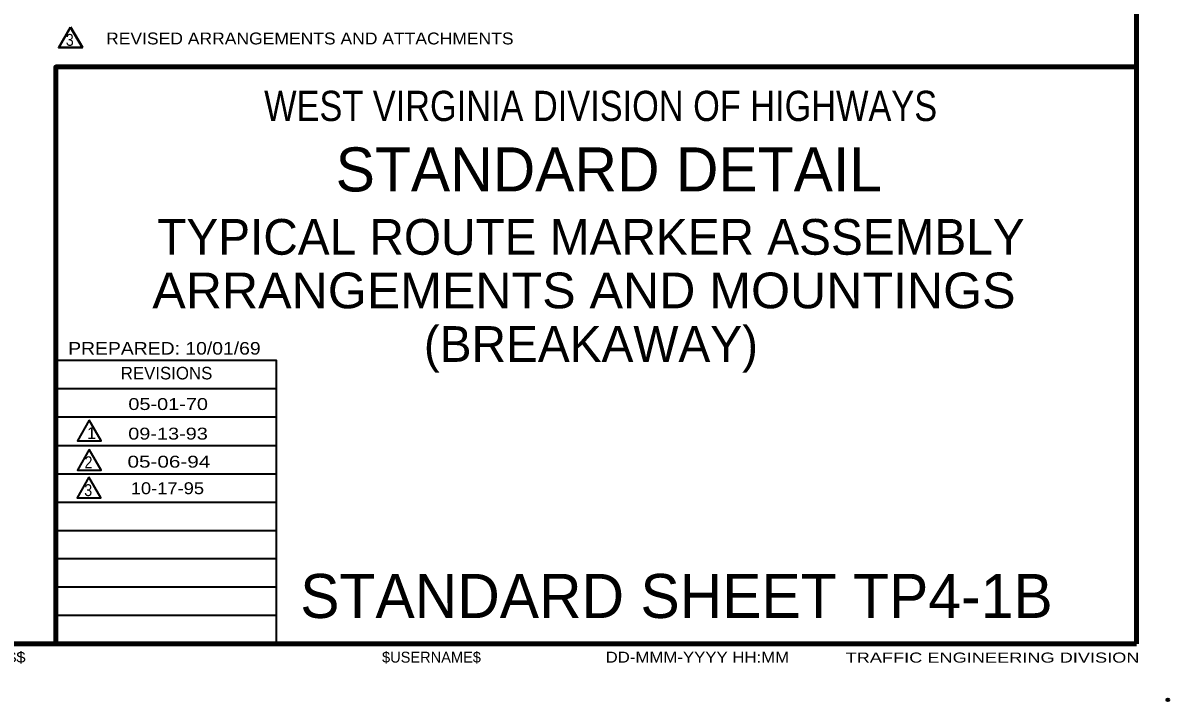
# Model space of a CAD drawing. Extents: x 851 to 1706, y -23 to 521.
# Drawn here: x 1475.1 to 1706.3, y -23.4 to 113.3 of the extents above; entities that cross this region are included whole.
import ezdxf
from ezdxf.enums import TextEntityAlignment as Align

# ---------------------------------------------------------------- set-up
doc = ezdxf.new("R2010")
doc.units = 0
doc.header["$PDMODE"] = 32
doc.header["$PDSIZE"] = 0.5
doc.layers.add('1', color=7, linetype='Continuous', lineweight=35)
doc.layers.add('61', color=7, linetype='Continuous', lineweight=35)

msp = doc.modelspace()

# ---------------------------------------------------------------- linework, layer by layer
at = {"layer": '1', "lineweight": 158}
for q in [(1699.744, 514.252), (1699.744, 104.452), (908.144, -11.848)]:
    msp.add_line((1699.744, -11.848), q, dxfattribs=at)
at = {"layer": '1', "lineweight": 13}
msp.add_line((1699.744, -11.848), (1699.744, 514.252), dxfattribs=at)
at = {"layer": '1'}
for p, q in [((1526.244, 39.552), (1481.744, 39.552)), ((1526.244, 33.852), (1481.744, 33.852)), ((1526.244, 28.052), (1481.744, 28.052)), ((1526.244, 22.352), (1481.744, 22.352)), ((1526.244, 16.652), (1481.744, 16.652)), ((1526.244, 10.952), (1481.744, 10.952)), ((1526.244, 5.252), (1481.744, 5.252)), ((1526.244, -0.448), (1481.744, -0.448)), ((1526.244, -6.148), (1481.744, -6.148))]:
    msp.add_line(p, q, dxfattribs=at)
at = {"layer": '1', "lineweight": 40}
msp.add_lwpolyline([(1484.724, 112.5), (1482.324, 108.343), (1487.124, 108.343)], close=True, dxfattribs=at)
at = {"layer": '1', "lineweight": 158}
msp.add_lwpolyline([(1481.744, -11.848), (1481.744, 104.452), (1699.744, 104.452)], dxfattribs=at)
at = {"layer": '1'}
msp.add_lwpolyline([(1526.244, -11.848), (1526.244, 45.252), (1481.744, 45.252)], dxfattribs=at)
for points in [[(1488.491, 33.219), (1486.091, 29.062), (1490.89, 29.062)], [(1488.492, 27.338), (1486.092, 23.182), (1490.892, 23.182)], [(1488.426, 21.718), (1486.026, 17.561), (1490.826, 17.561)]]:
    msp.add_lwpolyline(points, close=True, dxfattribs=at)
msp.add_point((1706.044, -23.148), dxfattribs=at)
at = {"layer": '61', "lineweight": 53}
for q in [(1547.044, -11.848), (1547.044, -11.848), (1547.044, -11.848), (1547.344, -11.848), (1547.344, -11.848)]:
    msp.add_line((1699.744, -11.848), q, dxfattribs=at)

# ---------------------------------------------------------------- texts
at = {"layer": '1'}
for s, height, width, p in [('3', 2.4, 0.9, (1484.572, 108.706)), ('REVISED ARRANGEMENTS AND ATTACHMENTS', 2.4, 1.1, (1532.986, 108.992)), ('WEST VIRGINIA DIVISION OF HIGHWAYS', 6.089, 0.85, (1591.644, 93.552)), ('ARRANGEMENTS AND MOUNTINGS ', 7.2, 1.05, (1589.68, 55.792)), ('05-01-70', 2.4, 1.25, (1504.407, 35.283)), ('09-13-93', 2.4, 1.25, (1504.383, 29.324)), ('2', 2.4, 0.9, (1488.34, 23.544)), ('05-06-94', 2.4, 1.3, (1504.558, 23.667)), ('3', 2.4, 0.9, (1488.284, 17.924)), ('10-17-95', 2.4, 1.15, (1504.256, 18.312))]:
    msp.add_text(s, height=height, dxfattribs=dict(at, width=width)).set_placement(p, align=Align.CENTER)
for s, height, p in [('STANDARD DETAIL', 8.881, (1593.294, 79.352)), ('TYPICAL ROUTE MARKER ASSEMBLY', 7.2, (1589.68, 66.592)), ('(BREAKAWAY)', 7.2, (1589.68, 44.992)), ('1', 2.4, (1488.955, 29.425))]:
    msp.add_text(s, height=height, dxfattribs=at).set_placement(p, align=Align.CENTER)
for s, height, width, p in [('PREPARED: 10/01/69', 2.537, 1.15, (1484.244, 46.452)), ('$$$$$$$$$FILENAME$$$$$$$$', 2.2, 1.15, (1426.744, -15.648)), ('DD-MMM-YYYY HH:MM', 2.2, 1.15, (1592.644, -15.648)), ('TRAFFIC ENGINEERING DIVISION', 2.031, 1.35, (1641.044, -15.648))]:
    msp.add_text(s, height=height, dxfattribs=dict(at, width=width)).set_placement(p)
for s, height, p in [('REVISIONS', 2.537, (1494.844, 41.452)), ('STANDARD SHEET TP4-1B', 8.881, (1531.044, -6.648)), ('$USERNAME$', 2.2, (1547.544, -15.648))]:
    msp.add_text(s, height=height, dxfattribs=at).set_placement(p)

doc.saveas('drawing.dxf')
